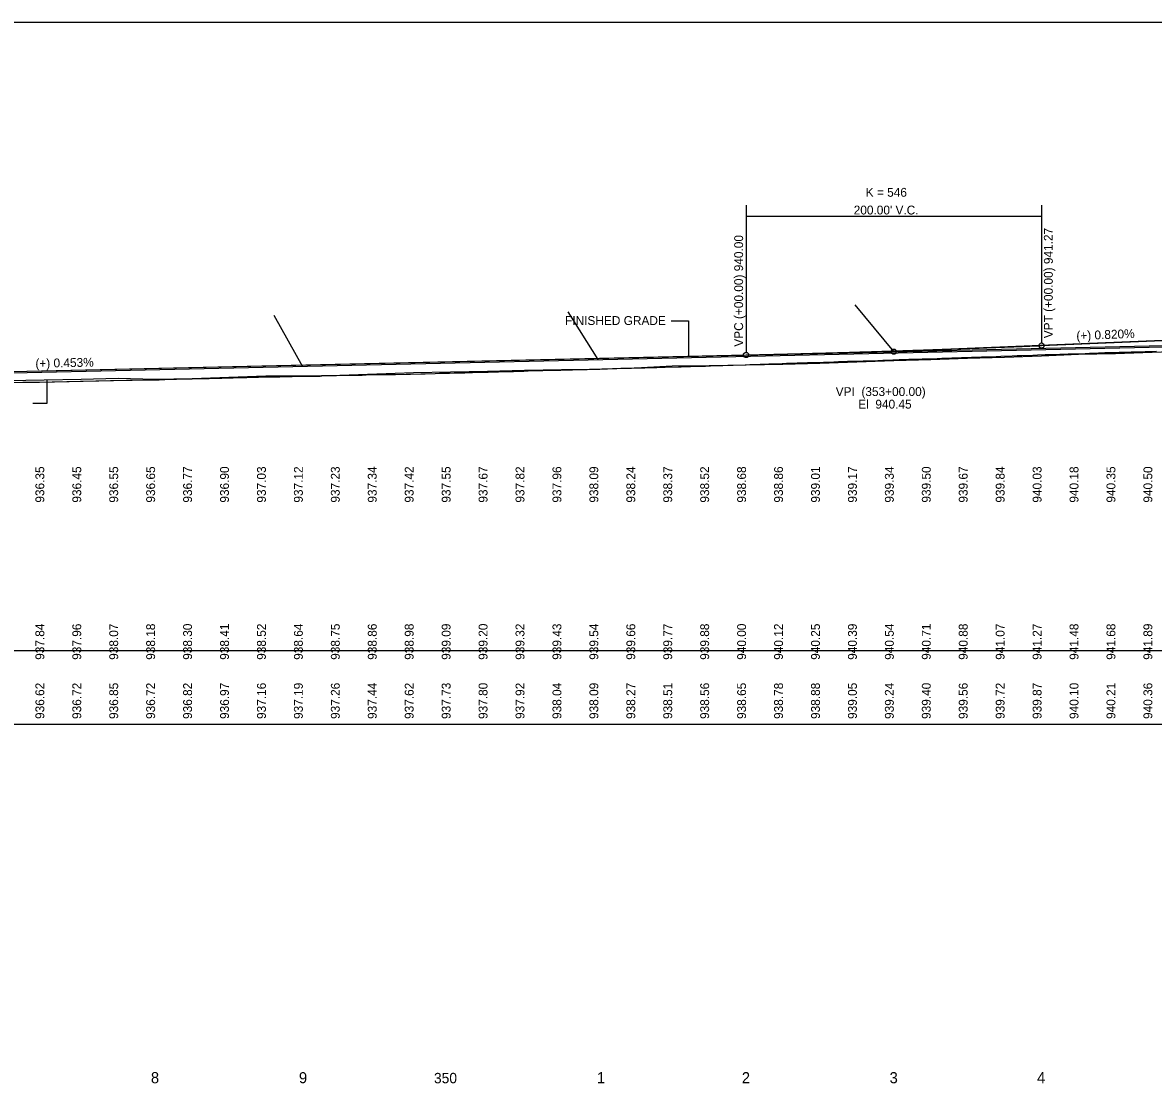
# Model space of a CAD drawing. Extents: x 120 to 1628239, y 505 to 1092823.
# Drawn here: x 1615249 to 1616014, y 1076164 to 1076882 of the extents above; entities that cross this region are included whole.
import ezdxf

# ---------------------------------------------------------------- set-up
doc = ezdxf.new("R2010")
doc.units = 0
for name, color, linetype in [('Default', 7, 'Continuous'), ('RD_DDB_EX_Tx', 7, 'Continuous'), ('RD_DDB_GradeTX', 7, 'Continuous'), ('RD_DDB_PI', 7, 'Continuous'), ('RD_DDB_PR_Tx', 7, 'Continuous'), ('RD_DDB_Profile_EX', 7, 'Continuous'), ('RD_DDB_Profile_PR', 7, 'Continuous'), ('RD_DDB_StaTX', 7, 'Continuous'), ('RD_DDB_StripGrade', 7, 'Continuous'), ('RD_DDB_StripGrade_PR', 7, 'Continuous'), ('RD_DDB_VCLbl', 7, 'Continuous'), ('RD_GPK_Profile_Cell', 7, 'Continuous'), ('RD_PD_Final_TrvlWay', 7, 'Continuous'), ('RD_Sketch10', 7, 'Continuous')]:
    doc.layers.add(name, color=color, linetype=linetype)

msp = doc.modelspace()

# ---------------------------------------------------------------- linework, layer by layer
at = {"layer": 'Default'}
for p, q in [((1615838.64, 1076659.56), (1616138.64, 1076671.86)), ((1615938.64, 1076663.66), (1616038.64, 1076667.76)), ((1614837.9, 1076636.86), (1615877.85, 1076660.43)), ((1614938.64, 1076639.15), (1615738.64, 1076657.29))]:
    msp.add_line(p, q, dxfattribs=at)
msp.add_lwpolyline([(1614738.64, 1076407.31), (1616238.64, 1076407.31), (1616238.64, 1076882.31), (1614738.64, 1076882.31)], close=True, dxfattribs=at)
msp.add_open_spline([(1615738.64, 1076657.29), (1615838.64, 1076659.56), (1615938.64, 1076663.66)], degree=2, dxfattribs=at)
at = {"layer": 'RD_DDB_EX_Tx'}
for p, q in [((1615265.65, 1076624.72), (1615265.65, 1076640.46)), ((1615255.94, 1076624.72), (1615265.65, 1076624.72))]:
    msp.add_line(p, q, dxfattribs=at)
at = {"layer": 'RD_DDB_PI'}
for p, q in [((1615928.57, 1076663.25), (1615840.39, 1076659.63)), ((1615748.66, 1076657.52), (1615836.89, 1076659.52))]:
    msp.add_line(p, q, dxfattribs=at)
msp.add_circle((1615838.64, 1076659.56), 1.75, dxfattribs=at)
at = {"layer": 'RD_DDB_PR_Tx'}
for p, q in [((1615687.85, 1076680.43), (1615699.72, 1076680.43)), ((1615699.72, 1076680.43), (1615699.72, 1076656.61))]:
    msp.add_line(p, q, dxfattribs=at)
at = {"layer": 'RD_DDB_Profile_EX'}
msp.add_lwpolyline([(1615238.64, 1076639.96), (1615263.64, 1076640.42), (1615288.64, 1076640.91), (1615313.64, 1076641.54), (1615338.64, 1076640.9), (1615363.64, 1076641.39), (1615388.64, 1076642.16), (1615413.64, 1076643.1), (1615438.64, 1076643.28), (1615463.64, 1076643.6), (1615488.64, 1076644.5), (1615513.64, 1076645.42), (1615538.64, 1076645.96), (1615563.64, 1076646.32), (1615588.64, 1076646.9), (1615613.64, 1076647.5), (1615638.64, 1076647.78), (1615663.64, 1076648.64), (1615688.64, 1076649.88), (1615713.64, 1076650.1), (1615738.64, 1076650.54), (1615763.64, 1076651.18), (1615788.64, 1076651.69), (1615813.64, 1076652.56), (1615838.64, 1076653.5), (1615863.64, 1076654.31), (1615888.64, 1076655.1), (1615913.64, 1076655.89), (1615938.64, 1076656.64), (1615963.64, 1076657.83), (1615988.64, 1076658.38), (1616013.64, 1076659.1), (1616038.64, 1076659.99)], dxfattribs=at)
at = {"layer": 'RD_DDB_Profile_PR'}
for p, q in [((1615938.64, 1076663.66), (1616038.64, 1076667.76)), ((1614938.64, 1076639.15), (1615738.64, 1076657.29))]:
    msp.add_line(p, q, dxfattribs=at)
msp.add_spline([(1615738.64, 1076657.29), (1615742.64, 1076657.38), (1615746.64, 1076657.48), (1615750.64, 1076657.57), (1615754.64, 1076657.67), (1615758.64, 1076657.76), (1615762.64, 1076657.86), (1615766.64, 1076657.96), (1615770.64, 1076658.06), (1615774.64, 1076658.17), (1615778.64, 1076658.27), (1615782.64, 1076658.38), (1615786.64, 1076658.49), (1615790.64, 1076658.59), (1615794.64, 1076658.7), (1615798.64, 1076658.82), (1615802.64, 1076658.93), (1615806.64, 1076659.04), (1615810.64, 1076659.16), (1615814.64, 1076659.28), (1615818.64, 1076659.4), (1615822.64, 1076659.52), (1615826.64, 1076659.64), (1615830.64, 1076659.76), (1615834.64, 1076659.89), (1615838.64, 1076660.02), (1615842.64, 1076660.14), (1615846.64, 1076660.27), (1615850.64, 1076660.41), (1615854.64, 1076660.54), (1615858.64, 1076660.67), (1615862.64, 1076660.81), (1615866.64, 1076660.94), (1615870.64, 1076661.08), (1615874.64, 1076661.22), (1615878.64, 1076661.36), (1615882.64, 1076661.51), (1615886.64, 1076661.65), (1615890.64, 1076661.8), (1615894.64, 1076661.94), (1615898.64, 1076662.09), (1615902.64, 1076662.24), (1615906.64, 1076662.39), (1615910.64, 1076662.55), (1615914.64, 1076662.7), (1615918.64, 1076662.86), (1615922.64, 1076663.01), (1615926.64, 1076663.17), (1615930.64, 1076663.33), (1615934.64, 1076663.5), (1615938.64, 1076663.66)], degree=3, dxfattribs=at)
at = {"layer": 'RD_DDB_VCLbl'}
for p, q in [((1615738.64, 1076758.66), (1615738.64, 1076659.04)), ((1615938.64, 1076758.66), (1615938.64, 1076665.41)), ((1615738.64, 1076751.16), (1615938.64, 1076751.16))]:
    msp.add_line(p, q, dxfattribs=at)
for centre in [(1615938.64, 1076663.66), (1615738.64, 1076657.29)]:
    msp.add_circle(centre, 1.75, dxfattribs=at)
at = {"layer": 'RD_GPK_Profile_Cell'}
msp.add_line((1609538.64, 1076457.31), (1626874.64, 1076457.31), dxfattribs=at)
at = {"layer": 'RD_PD_Final_TrvlWay'}
for p, q in [((1615438.64, 1076649.36), (1615419.2, 1076684.11)), ((1615638.64, 1076654.16), (1615618.18, 1076686.45)), ((1615838.64, 1076659.56), (1615812.48, 1076691.14)), ((1616138.64, 1076671.86), (1615838.64, 1076659.56)), ((1614737.59, 1076634.58), (1616087.83, 1076665.19)), ((1614737.59, 1076633.73), (1616087.83, 1076664.34))]:
    msp.add_line(p, q, dxfattribs=at)
at = {"layer": 'RD_Sketch10'}
for points in [[(1615375.26, 1076641.43), (1615380.8, 1076641.54), (1615383.88, 1076641.64), (1615391.42, 1076641.91), (1615393.09, 1076641.97), (1615400.63, 1076642.14), (1615401.42, 1076642.17), (1615408.74, 1076642.37), (1615411.2, 1076642.43), (1615418.93, 1076642.51), (1615421.42, 1076642.56), (1615423.16, 1076642.6), (1615430.64, 1076642.72), (1615431.43, 1076642.74), (1615438.87, 1076642.9), (1615441.43, 1076642.95), (1615447.8, 1076642.99), (1615450.39, 1076643.05), (1615451.42, 1076643.06), (1615459.83, 1076643.38), (1615461.43, 1076643.42), (1615468.76, 1076643.54), (1615471.43, 1076643.59), (1615478.73, 1076643.72), (1615481.43, 1076643.78), (1615487.43, 1076643.96), (1615489.99, 1076644.01), (1615498.47, 1076644.1), (1615501.44, 1076644.14), (1615508.61, 1076644.32), (1615511.44, 1076644.39), (1615518.59, 1076644.52), (1615521.46, 1076644.59), (1615528.27, 1076644.8), (1615531.12, 1076644.88), (1615535.02, 1076644.98), (1615537.86, 1076645.04), (1615541.12, 1076645.1), (1615548.25, 1076645.29), (1615551.13, 1076645.37), (1615553.42, 1076645.41), (1615560.55, 1076645.59), (1615564.03, 1076645.67), (1615571.13, 1076645.96), (1615574.44, 1076646.03), (1615577.41, 1076646.14), (1615581.16, 1076646.21), (1615588.25, 1076646.39), (1615591.13, 1076646.47), (1615598.24, 1076646.69), (1615601.13, 1076646.78), (1615609.77, 1076646.99), (1615613.28, 1076647.1), (1615618.92, 1076647.23), (1615621.12, 1076647.26), (1615628.27, 1076647.47), (1615631.12, 1076647.55), (1615632.61, 1076647.58), (1615639.74, 1076647.79), (1615641.12, 1076647.83), (1615648.26, 1076648.04), (1615651.12, 1076648.14), (1615653.79, 1076648.25), (1615656.65, 1076648.32), (1615661.12, 1076648.44), (1615662.91, 1076648.49), (1615670.08, 1076648.66), (1615671.12, 1076648.7), (1615678.32, 1076648.88), (1615681.12, 1076648.97), (1615683.95, 1076649.04), (1615692.96, 1076649.29), (1615694.83, 1076649.34), (1615700.17, 1076649.45), (1615701.12, 1076649.48), (1615708.16, 1076649.73), (1615711.13, 1076649.8), (1615718.07, 1076650.09), (1615720.92, 1076650.19), (1615722.98, 1076650.25), (1615728.64, 1076650.4), (1615729.9, 1076650.46), (1615738.04, 1076650.71), (1615741.18, 1076650.8), (1615748.11, 1076651.07), (1615751.13, 1076651.16), (1615754.17, 1076651.26), (1615763.02, 1076651.6), (1615766.01, 1076651.72), (1615771.13, 1076651.84), (1615773.26, 1076651.88), (1615780.27, 1076652.12), (1615784.17, 1076652.24), (1615791.13, 1076652.44), (1615798.05, 1076652.71), (1615801.14, 1076652.78), (1615804.08, 1076652.91), (1615807.2, 1076653.04), (1615811.14, 1076653.07), (1615818, 1076653.27), (1615820.93, 1076653.35)], [(1615820.93, 1076653.35), (1615827.76, 1076653.62), (1615831.14, 1076653.73), (1615837.97, 1076653.96), (1615841.14, 1076654.07), (1615842.26, 1076654.12), (1615846.75, 1076654.31), (1615848.82, 1076654.38), (1615851.14, 1076654.39), (1615857.95, 1076654.6), (1615861.15, 1076654.72), (1615867.93, 1076654.93), (1615871.15, 1076655.03), (1615877.9, 1076655.28), (1615881.99, 1076655.42), (1615884.4, 1076655.54), (1615888.74, 1076655.67), (1615891.15, 1076655.74), (1615897.92, 1076655.95), (1615901.15, 1076656.07), (1615907.95, 1076656.3), (1615911.14, 1076656.42), (1615918.88, 1076656.72), (1615922.04, 1076656.83), (1615925.2, 1076656.95), (1615932.65, 1076657.25), (1615935.83, 1076657.36), (1615941.16, 1076657.53), (1615948, 1076657.69), (1615951.14, 1076657.79), (1615953.42, 1076657.87), (1615956.62, 1076657.97), (1615961.23, 1076658.14), (1615968.14, 1076658.35), (1615971.13, 1076658.47), (1615973.88, 1076658.55), (1615977.28, 1076658.68), (1615981.47, 1076658.87), (1615988.41, 1076659.07), (1615991.13, 1076659.15), (1615995.59, 1076659.3), (1615999.28, 1076659.38), (1616001.79, 1076659.5), (1616008.78, 1076659.68), (1616011.12, 1076659.75), (1616016.51, 1076659.91)], [(1615238.47, 1076638.55), (1615249.08, 1076638.79), (1615250.8, 1076638.83), (1615256.77, 1076638.91), (1615257.89, 1076638.93), (1615260.48, 1076638.98), (1615268.9, 1076639.18), (1615270.5, 1076639.21), (1615278.81, 1076639.36), (1615280.52, 1076639.39), (1615288.21, 1076639.55), (1615289.94, 1076639.58), (1615298.54, 1076639.75), (1615300.54, 1076639.8), (1615308.56, 1076639.94), (1615310.55, 1076639.99), (1615319.33, 1076640.13), (1615321.4, 1076640.17), (1615323.13, 1076640.19), (1615331.04, 1076640.38), (1615334.49, 1076640.47), (1615336.92, 1076640.52), (1615341.41, 1076640.57), (1615349.2, 1076640.82), (1615351.41, 1076640.88), (1615353.21, 1076640.92), (1615360.96, 1076641.11), (1615363.75, 1076641.15), (1615373.44, 1076641.4), (1615375.26, 1076641.43)]]:
    msp.add_lwpolyline(points, dxfattribs=at)

# ---------------------------------------------------------------- texts
at = {"layer": 'Default'}
for s, p in [('936.35', (1615263.64, 1076557.31)), ('936.45', (1615288.64, 1076557.31)), ('936.55', (1615313.64, 1076557.31)), ('936.65', (1615338.64, 1076557.31)), ('936.77', (1615363.64, 1076557.31)), ('936.90', (1615388.64, 1076557.31)), ('937.03', (1615413.64, 1076557.31)), ('937.12', (1615438.64, 1076557.31)), ('937.23', (1615463.64, 1076557.31)), ('937.34', (1615488.64, 1076557.31)), ('937.42', (1615513.64, 1076557.31)), ('937.55', (1615538.64, 1076557.31)), ('937.67', (1615563.64, 1076557.31)), ('937.82', (1615588.64, 1076557.31)), ('937.96', (1615613.64, 1076557.31)), ('938.09', (1615638.64, 1076557.31)), ('938.24', (1615663.64, 1076557.31)), ('938.37', (1615688.64, 1076557.31)), ('938.52', (1615713.64, 1076557.31)), ('938.68', (1615738.64, 1076557.31)), ('938.86', (1615763.64, 1076557.31)), ('939.01', (1615788.64, 1076557.31)), ('939.17', (1615813.64, 1076557.31)), ('939.34', (1615838.64, 1076557.31)), ('939.50', (1615863.64, 1076557.31)), ('939.67', (1615888.64, 1076557.31)), ('939.84', (1615913.64, 1076557.31)), ('940.03', (1615938.64, 1076557.31)), ('940.18', (1615963.64, 1076557.31)), ('940.35', (1615988.64, 1076557.31)), ('940.50', (1616013.64, 1076557.31))]:
    msp.add_text(s, height=6, rotation=90, dxfattribs=at).set_placement(p)
at = {"layer": 'RD_DDB_GradeTX'}
for s, rotation, p in [('(+) 0.820%', 2.34781, (1615962.34, 1076667.28)), ('(+) 0.453%', 1.29894, (1615257.7, 1076648.56))]:
    msp.add_text(s, height=6, rotation=rotation, dxfattribs=at).set_placement(p)
at = {"layer": 'RD_DDB_PI'}
for s, p in [('VPI  (353+00.00)', (1615799.34, 1076629.49)), ('El  940.45', (1615814.58, 1076620.99))]:
    msp.add_text(s, height=6, dxfattribs=at).set_placement(p)
at = {"layer": 'RD_DDB_PR_Tx'}
msp.add_text('FINISHED GRADE', height=6, dxfattribs=at).set_placement((1615616.15, 1076677.6))
at = {"layer": 'RD_DDB_StaTX'}
for s, height, p in [('8', 7.5, (1615335.8, 1076164.25)), ('9', 7.5, (1615436, 1076164.25)), ('350', 7, (1615527.4, 1076164.25)), ('1', 7.5, (1615637.64, 1076164.25)), ('2', 7.5, (1615735.8, 1076164.25)), ('3', 7.5, (1615835.8, 1076164.25)), ('4', 7.5, (1615935.6, 1076164.25))]:
    msp.add_text(s, height=height, dxfattribs=at).set_placement(p)
at = {"layer": 'RD_DDB_StripGrade'}
for s, p in [('936.62', (1615263.64, 1076410.85)), ('936.72', (1615288.64, 1076410.85)), ('936.85', (1615313.64, 1076410.85)), ('936.72', (1615338.64, 1076410.85)), ('936.82', (1615363.64, 1076410.85)), ('936.97', (1615388.64, 1076410.85)), ('937.16', (1615413.64, 1076410.85)), ('937.19', (1615438.64, 1076410.85)), ('937.26', (1615463.64, 1076410.85)), ('937.44', (1615488.64, 1076410.85)), ('937.62', (1615513.64, 1076410.85)), ('937.73', (1615538.64, 1076410.85)), ('937.80', (1615563.64, 1076410.85)), ('937.92', (1615588.64, 1076410.85)), ('938.04', (1615613.64, 1076410.85)), ('938.09', (1615638.64, 1076410.85)), ('938.27', (1615663.64, 1076410.85)), ('938.51', (1615688.64, 1076410.85)), ('938.56', (1615713.64, 1076410.85)), ('938.65', (1615738.64, 1076410.85)), ('938.78', (1615763.64, 1076410.85)), ('938.88', (1615788.64, 1076410.85)), ('939.05', (1615813.64, 1076410.85)), ('939.24', (1615838.64, 1076410.85)), ('939.40', (1615863.64, 1076410.85)), ('939.56', (1615888.64, 1076410.85)), ('939.72', (1615913.64, 1076410.85)), ('939.87', (1615938.64, 1076410.85)), ('940.10', (1615963.64, 1076410.85)), ('940.21', (1615988.64, 1076410.85)), ('940.36', (1616013.64, 1076410.85))]:
    msp.add_text(s, height=6, rotation=90, dxfattribs=at).set_placement(p)
at = {"layer": 'RD_DDB_StripGrade_PR'}
for s, p in [('937.84', (1615263.64, 1076450.9)), ('937.96', (1615288.64, 1076450.9)), ('938.07', (1615313.64, 1076450.9)), ('938.18', (1615338.64, 1076450.9)), ('938.30', (1615363.64, 1076450.9)), ('938.41', (1615388.64, 1076450.9)), ('938.52', (1615413.64, 1076450.9)), ('938.64', (1615438.64, 1076450.9)), ('938.75', (1615463.64, 1076450.9)), ('938.86', (1615488.64, 1076450.9)), ('938.98', (1615513.64, 1076450.9)), ('939.09', (1615538.64, 1076450.9)), ('939.20', (1615563.64, 1076450.9)), ('939.32', (1615588.64, 1076450.9)), ('939.43', (1615613.64, 1076450.9)), ('939.54', (1615638.64, 1076450.9)), ('939.66', (1615663.64, 1076450.9)), ('939.77', (1615688.64, 1076450.9)), ('939.88', (1615713.64, 1076450.9)), ('940.00', (1615738.64, 1076450.9)), ('940.12', (1615763.64, 1076450.9)), ('940.25', (1615788.64, 1076450.9)), ('940.39', (1615813.64, 1076450.9)), ('940.54', (1615838.64, 1076450.9)), ('940.71', (1615863.64, 1076450.9)), ('940.88', (1615888.64, 1076450.9)), ('941.07', (1615913.64, 1076450.9)), ('941.27', (1615938.64, 1076450.9)), ('941.48', (1615963.64, 1076450.9)), ('941.68', (1615988.64, 1076450.9)), ('941.89', (1616013.64, 1076450.9))]:
    msp.add_text(s, height=6, rotation=90, dxfattribs=at).set_placement(p)
at = {"layer": 'RD_DDB_VCLbl'}
for s, p in [('K = 546', (1615819.66, 1076764.41)), ("200.00' V.C.", (1615811.51, 1076752.41))]:
    msp.add_text(s, height=6, dxfattribs=at).set_placement(p)
for s, p in [('VPC (+00.00) 940.00', (1615736.64, 1076662.89)), ('VPT (+00.00) 941.27', (1615946.26, 1076668.62))]:
    msp.add_text(s, height=6, rotation=90, dxfattribs=at).set_placement(p)

doc.saveas('drawing.dxf')
